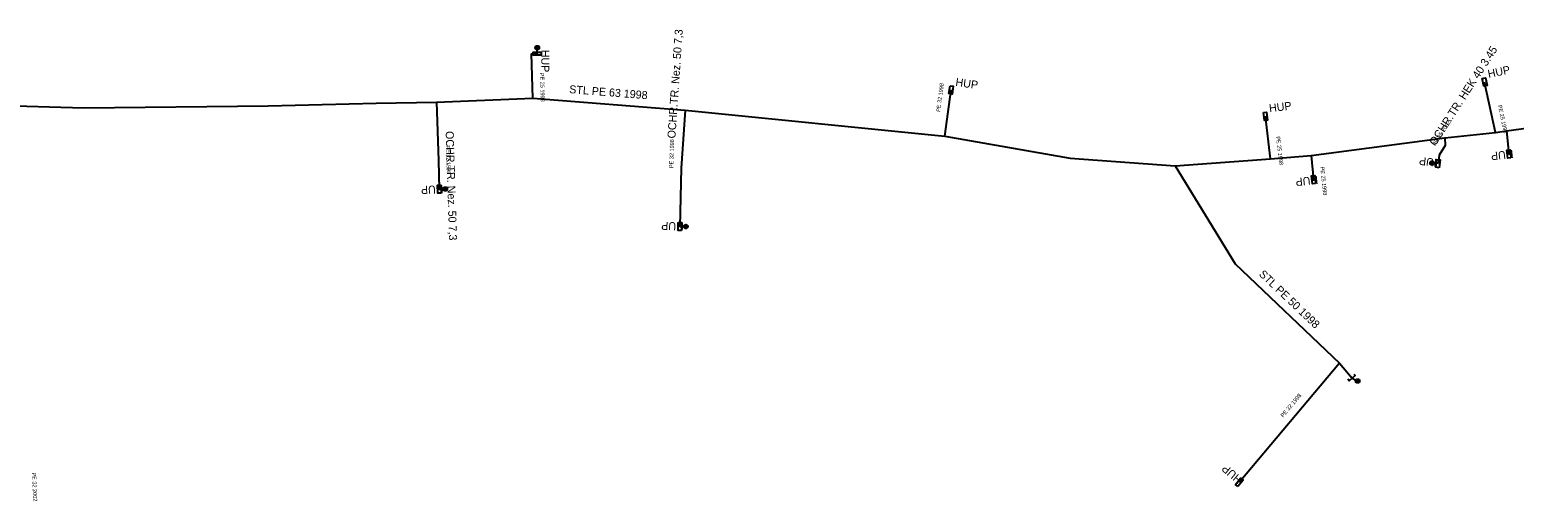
# Model space of a CAD drawing. Extents: x -741240 to -740302, y -1028024 to -1027535.
# Drawn here: x -740664.5 to -740479, y -1027839.8 to -1027781 of the extents above; entities that cross this region are included whole.
import ezdxf

# ---------------------------------------------------------------- set-up
doc = ezdxf.new("R2010")
doc.units = 0
for name, color, linetype in [('ST OP Chráni_ka - provoz', 7, 'Continuous'), ('ST Úsek p_ípojky - provoz', 7, 'Continuous'), ('ST Úsek plynovodu - provoz', 7, 'Continuous'), ('ST_HUP_22_23_popis', 7, 'Continuous'), ('Vrstva 1', 7, 'Continuous')]:
    doc.layers.add(name, color=color, linetype=linetype)

msp = doc.modelspace()

# ---------------------------------------------------------------- linework, layer by layer
at = {"layer": 'ST OP Chráni_ka - provoz'}
for points in [[(-740613.68, -1027790.09), (-740613.45, -1027797.37)], [(-740582.6, -1027791.09), (-740583.1, -1027798.32)], [(-740487.66, -1027794.54), (-740487.61, -1027795.51)], [(-740488.39, -1027796.72), (-740488.52, -1027797.75)], [(-740487.61, -1027795.51), (-740488.39, -1027796.72)]]:
    msp.add_lwpolyline(points, dxfattribs=at)
at = {"layer": 'ST Úsek p_ípojky - provoz'}
for points in [[(-740601.67, -1027789.58), (-740601.81, -1027784.02), (-740601.1, -1027784.02)], [(-740481.34, -1027793.85), (-740482.69, -1027787.56)], [(-740550.15, -1027794.34), (-740549.38, -1027788.54)], [(-740613.68, -1027790.09), (-740613.45, -1027797.37), (-740613.35, -1027800.96)], [(-740582.6, -1027791.09), (-740583.1, -1027798.32), (-740583.28, -1027805.61)], [(-740509.44, -1027797.15), (-740510.08, -1027791.84)], [(-740487.66, -1027794.54), (-740487.61, -1027795.51), (-740488.39, -1027796.72), (-740488.52, -1027797.75)], [(-740479.98, -1027793.64), (-740479.65, -1027796.55)], [(-740504.39, -1027796.76), (-740504.07, -1027799.78)], [(-740500.85, -1027822.72), (-740513.36, -1027837.6)]]:
    msp.add_lwpolyline(points, dxfattribs=at)
at = {"layer": 'ST Úsek plynovodu - provoz'}
for points in [[(-740521.37, -1027798.02), (-740509.44, -1027797.15), (-740504.39, -1027796.76), (-740487.66, -1027794.54), (-740481.34, -1027793.85), (-740479.98, -1027793.64), (-740464.98, -1027791.6), (-740449.4, -1027789.47), (-740435.23, -1027787.47), (-740420.2, -1027785.01)], [(-740673.51, -1027790.31), (-740657.76, -1027790.8), (-740634.73, -1027790.54), (-740621.24, -1027790.21), (-740613.68, -1027790.09), (-740601.67, -1027789.58), (-740582.6, -1027791.09), (-740550.15, -1027794.34), (-740534.5, -1027797.08), (-740521.37, -1027798.02)], [(-740521.37, -1027798.02), (-740513.86, -1027810.3), (-740500.85, -1027822.72), (-740499.24, -1027824.58)]]:
    msp.add_lwpolyline(points, dxfattribs=at)
at = {"layer": 'Vrstva 1'}
for p, q in [((-740601.1, -1027784.02), (-740601.1, -1027783.52)), ((-740488.52, -1027797.75), (-740489.02, -1027797.71)), ((-740613.35, -1027800.96), (-740612.85, -1027800.94)), ((-740583.28, -1027805.61), (-740582.78, -1027805.62)), ((-740499.24, -1027824.58), (-740498.79, -1027824.81))]:
    msp.add_line(p, q, dxfattribs=at)
for points in [[(-740600.6, -1027783.82), (-740600.6, -1027784.22), (-740601.6, -1027784.22), (-740601.6, -1027783.82)], [(-740482.99, -1027787.11), (-740482.6, -1027787.03), (-740482.39, -1027788.01), (-740482.78, -1027788.09)], [(-740549.51, -1027788.02), (-740549.11, -1027788.07), (-740549.25, -1027789.06), (-740549.65, -1027789.01)], [(-740510.34, -1027791.37), (-740509.94, -1027791.32), (-740509.82, -1027792.31), (-740510.22, -1027792.36)], [(-740488.38, -1027798.27), (-740488.78, -1027798.22), (-740488.66, -1027797.23), (-740488.26, -1027797.28)], [(-740479.4, -1027797.03), (-740479.8, -1027797.07), (-740479.9, -1027796.07), (-740479.5, -1027796.03)], [(-740613.13, -1027801.45), (-740613.53, -1027801.47), (-740613.57, -1027800.47), (-740613.17, -1027800.45)], [(-740503.82, -1027800.26), (-740504.22, -1027800.3), (-740504.32, -1027799.3), (-740503.92, -1027799.26)], [(-740583.09, -1027806.11), (-740583.49, -1027806.1), (-740583.47, -1027805.1), (-740583.07, -1027805.11)], [(-740513.53, -1027838.11), (-740513.83, -1027837.85), (-740513.19, -1027837.09), (-740512.88, -1027837.34)]]:
    msp.add_lwpolyline(points, close=True, dxfattribs=at)
msp.add_lwpolyline([(-740499.03, -1027824.06), (-740498.86, -1027824.25), (-740499.62, -1027824.91), (-740499.78, -1027824.72)], dxfattribs=at)
for centre, radius in [((-740601.1, -1027783.27), 0.249), ((-740601.21, -1027783.28), 0.0614), ((-740601, -1027783.28), 0.0614), ((-740489.27, -1027797.69), 0.249), ((-740489.27, -1027797.79), 0.0614), ((-740489.25, -1027797.59), 0.0614), ((-740612.6, -1027800.93), 0.249), ((-740612.61, -1027800.83), 0.0614), ((-740612.61, -1027801.03), 0.0614), ((-740582.53, -1027805.62), 0.249), ((-740582.54, -1027805.52), 0.0614), ((-740582.54, -1027805.72), 0.0614), ((-740498.57, -1027824.93), 0.249), ((-740498.63, -1027825.01), 0.0614), ((-740498.53, -1027824.83), 0.0614)]:
    msp.add_circle(centre, radius, dxfattribs=at)

# ---------------------------------------------------------------- texts
at = {"layer": 'ST OP Chráni_ka - provoz'}
for s, rotation, p in [('OCHR.TR. Nez. 50 7,3', 86.0439, (-740583.85, -1027794.64)), ('OCHR.TR. HEK 40 3.45', 57.193, (-740488.86, -1027795.6)), ('OCHR.TR. Nez. 50 7,3', 271.8096, (-740612.56, -1027793.7))]:
    msp.add_text(s, height=1, rotation=rotation, dxfattribs=at).set_placement(p)
at = {"layer": 'ST Úsek p_ípojky - provoz'}
for s, rotation, p in [('PE 25 1998', 271.4424, (-740600.75, -1027786.42)), ('PE 32 1998', 82.439, (-740550.76, -1027791.31)), ('PE 25 1998', 282.1028, (-740481.04, -1027790.49)), ('PE 25 2002', 57.193, (-740488.86, -1027795.6)), ('PE 32 1998', 88.5854, (-740584.1, -1027798.32)), ('PE 25 1998', 276.8619, (-740508.77, -1027794.38)), ('PE 32 1998', 271.8096, (-740612.51, -1027795.49)), ('PE 25 1998', 276.0485, (-740503.24, -1027798.16)), ('PE 32 1998', 49.9457, (-740507.87, -1027829.52)), ('PE 32 2002', 272.4265, (-740664.25, -1027836.38))]:
    msp.add_text(s, height=0.5, rotation=rotation, dxfattribs=at).set_placement(p)
at = {"layer": 'ST Úsek plynovodu - provoz'}
for s, rotation, p in [('STL PE 63 1998', 355.4727, (-740597.14, -1027788.94)), ('STL PE 50 1998', 316.3291, (-740510.98, -1027811.67))]:
    msp.add_text(s, height=1, rotation=rotation, dxfattribs=at).set_placement(p)
at = {"layer": 'ST_HUP_22_23_popis'}
for rotation, p in [(270, (-740600.6, -1027783.52)), (12, (-740482.19, -1027787.06)), (352, (-740548.88, -1027788.04)), (7, (-740509.58, -1027791.34)), (173, (-740488.02, -1027797.25)), (186, (-740479.15, -1027796.05)), (182, (-740612.85, -1027800.46)), (186, (-740503.57, -1027799.28)), (178.59, (-740582.78, -1027805.11)), (140, (-740512.86, -1027837.1))]:
    msp.add_text('HUP', height=1, rotation=rotation, dxfattribs=at).set_placement(p)

doc.saveas('drawing.dxf')
